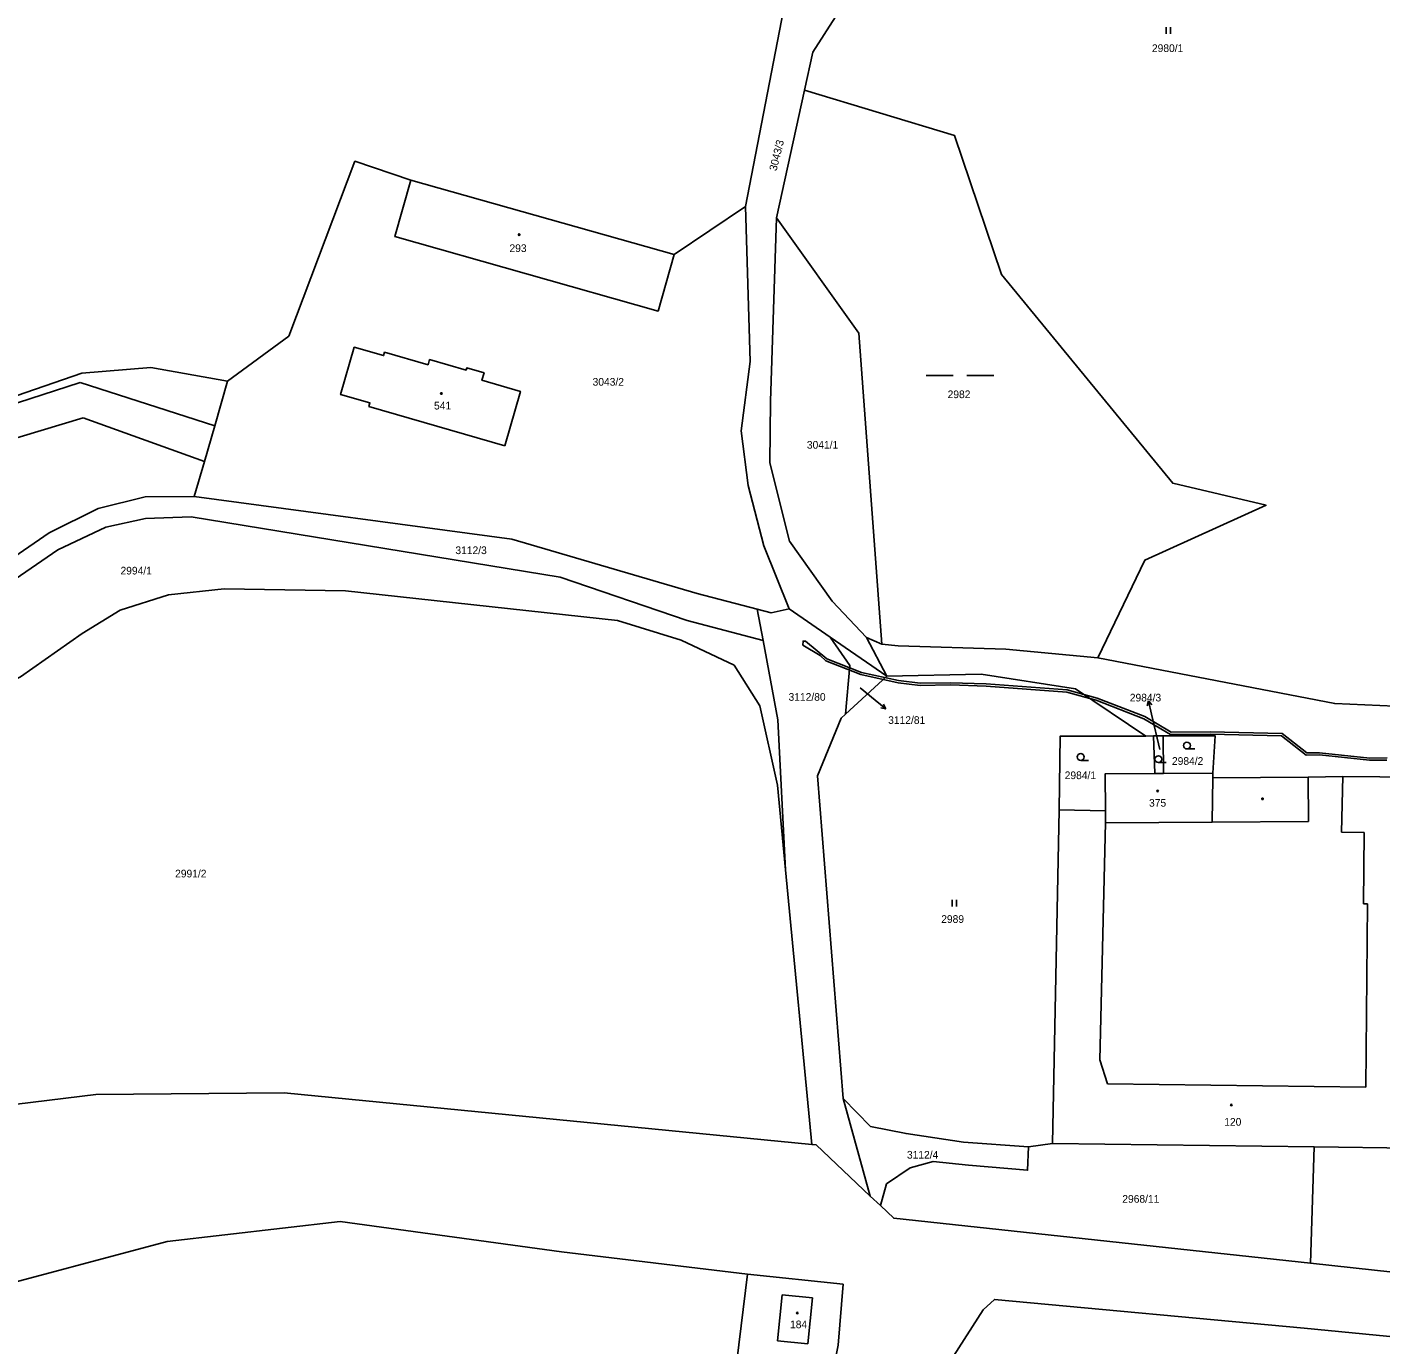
# Model space of a CAD drawing. Extents: x -776734 to -748832, y -1118122 to -976986.
# Drawn here: x -755036.1 to -754735.9, y -1113434.4 to -1113142 of the extents above; entities that cross this region are included whole.
import ezdxf

# ---------------------------------------------------------------- set-up
doc = ezdxf.new("R2010")
doc.units = 0
for name, color, linetype in [('KM_Hranice parcel', 7, 'Continuous'), ('KM_Parcelní čísla', 7, 'Continuous'), ('KM_Pop  PČ popisy', 7, 'Continuous'), ('KM_Vnitřní kresba', 7, 'Continuous'), ('KM_Věcná břemena k části', 7, 'Continuous'), ('KM_Značky budov', 7, 'Continuous'), ('KM_Značky kultur', 7, 'Continuous')]:
    doc.layers.add(name, color=color, linetype=linetype)

msp = doc.modelspace()

# ---------------------------------------------------------------- linework, layer by layer
at = {"layer": 'KM_Hranice parcel'}
for p, q in [((-754863.72, -1113156.03), (-754869.94, -1113184.37)), ((-754892.65, -1113192.47), (-754951.06, -1113175.96)), ((-754892.65, -1113192.47), (-754876.8, -1113181.8)), ((-755024.36, -1113220.91), (-754994.54, -1113230.49)), ((-754991.69, -1113220.6), (-754994.54, -1113230.49)), ((-754996.82, -1113238.38), (-755023.74, -1113228.7)), ((-754994.54, -1113230.49), (-754996.82, -1113238.38)), ((-754999.06, -1113246.17), (-754996.82, -1113238.38)), ((-754872.91, -1113278.1), (-754874.21, -1113271.18)), ((-754867.15, -1113271.08), (-754858.08, -1113277.36)), ((-754858.08, -1113277.36), (-754845.51, -1113286.05)), ((-754845.51, -1113286.05), (-754849.99, -1113277.44)), ((-754849.99, -1113277.44), (-754846.6, -1113278.91)), ((-754845.51, -1113286.05), (-754854.65, -1113294.42)), ((-754788.07, -1113299.3), (-754786.37, -1113299.29)), ((-754786.37, -1113299.29), (-754784.2, -1113299.29)), ((-754786.05, -1113307.61), (-754786.37, -1113299.29)), ((-754784.2, -1113299.29), (-754784.1, -1113307.6)), ((-754784.1, -1113307.6), (-754786.05, -1113307.61)), ((-754773.2, -1113307.52), (-754784.1, -1113307.6)), ((-754773.2, -1113308.57), (-754773.2, -1113307.52)), ((-754807.25, -1113315.67), (-754808.75, -1113389.67)), ((-754797.02, -1113315.93), (-754807.25, -1113315.67)), ((-754862.13, -1113389.91), (-754867.94, -1113328.97)), ((-754855.18, -1113379.69), (-754849.14, -1113401.34)), ((-754808.75, -1113389.67), (-754814.04, -1113390.4)), ((-754808.75, -1113389.67), (-754750.75, -1113390.44)), ((-754751.53, -1113416.27), (-754750.75, -1113390.44)), ((-754750.75, -1113390.44), (-754729.18, -1113390.74)), ((-754846.91, -1113403.45), (-754849.14, -1113401.34)), ((-754876.41, -1113418.71), (-754855.14, -1113420.87))]:
    msp.add_line(p, q, dxfattribs=at)
for points in [[(-754876.8, -1113181.8), (-754867.92, -1113135.91), (-754868.05, -1113104.5), (-754872.69, -1113085.2), (-754875.35, -1113079.52)], [(-754863.4, -1113082.6), (-754862.14, -1113085.88), (-754857.77, -1113108.41), (-754856.89, -1113139.77), (-754861.88, -1113147.63), (-754863.72, -1113156.03)], [(-755271.99, -1113090.82), (-755203.36, -1113173.85), (-755194.33, -1113180.41), (-755178.9, -1113182.49), (-755170.78, -1113184.63), (-755163.56, -1113188.38), (-755152.18, -1113198.82), (-755136.79, -1113213.94), (-755123.32, -1113222.34), (-755100.26, -1113228.77), (-755075.61, -1113229.77), (-755042.7, -1113225.27), (-755023.99, -1113218.77), (-755008.73, -1113217.54), (-754991.69, -1113220.6)], [(-754863.72, -1113156.03), (-754830.47, -1113166.06), (-754820.07, -1113196.9), (-754782.06, -1113243.24), (-754761.39, -1113248.09), (-754788.23, -1113260.27), (-754798.66, -1113281.97)], [(-754991.69, -1113220.6), (-754978.07, -1113210.56), (-754963.43, -1113171.79), (-754951.06, -1113175.96)], [(-754951.06, -1113175.96), (-754954.61, -1113188.52), (-754896.2, -1113205.03), (-754892.65, -1113192.47)], [(-754867.15, -1113271.08), (-754872.78, -1113257.09), (-754876.2, -1113243.72), (-754877.78, -1113231.6), (-754875.8, -1113216.25), (-754876.8, -1113181.8)], [(-754869.94, -1113184.37), (-754871.31, -1113225.02), (-754871.39, -1113238.69), (-754867.07, -1113256.05), (-754857.6, -1113269.39), (-754849.99, -1113277.44)], [(-754869.94, -1113184.37), (-754851.67, -1113209.94), (-754846.6, -1113278.91)], [(-754930.2, -1113234.9), (-754926.74, -1113222.86), (-754935.27, -1113220.39), (-754934.8, -1113218.76), (-754938.64, -1113217.65), (-754938.78, -1113218.13), (-754946.88, -1113215.78), (-754947.22, -1113216.93), (-754956.87, -1113214.15), (-754957.1, -1113214.92), (-754963.57, -1113213.05), (-754966.61, -1113223.54), (-754960.13, -1113225.41), (-754960.35, -1113226.17), (-754930.2, -1113234.9)], [(-755158.62, -1113218.61), (-755108.52, -1113234.11), (-755071.57, -1113236.21), (-755024.36, -1113220.91)], [(-755023.74, -1113228.7), (-755070.36, -1113242.74), (-755108.84, -1113241.5), (-755159.61, -1113226.16)], [(-755120.7, -1113319.55), (-755113.95, -1113312.75), (-755104.46, -1113304.58), (-755031.27, -1113254.22), (-755020.41, -1113248.82), (-755009.94, -1113246.24), (-754999.06, -1113246.17)], [(-754999.06, -1113246.17), (-754928.64, -1113255.61), (-754887.53, -1113267.69), (-754874.21, -1113271.18)], [(-754872.91, -1113278.1), (-754889.79, -1113273.69), (-754917.91, -1113264.06), (-754999.78, -1113250.7), (-755009.85, -1113251.04), (-755018.69, -1113252.95), (-755029.32, -1113258.02), (-755101.96, -1113307.9), (-755110.99, -1113316.94), (-755117.61, -1113328.97)], [(-754867.94, -1113328.97), (-754869.73, -1113310.2), (-754873.67, -1113292.58), (-754879.34, -1113283.56), (-754891.12, -1113278.02), (-754905.23, -1113273.67), (-754965.5, -1113267.11), (-754992.42, -1113266.68), (-755004.79, -1113267.98), (-755015.53, -1113271.37), (-755023.91, -1113276.56), (-755037.57, -1113286.2), (-755092.28, -1113314.49), (-755100.65, -1113318.43), (-755105.93, -1113322.81), (-755108.91, -1113328.1), (-755109.95, -1113335.16), (-755109.4, -1113341.3), (-755094.9, -1113384.72), (-755087.39, -1113386.98)], [(-754874.21, -1113271.18), (-754871.14, -1113271.98), (-754867.15, -1113271.08)], [(-754867.94, -1113328.97), (-754869.62, -1113295.67), (-754872.91, -1113278.1)], [(-754854.65, -1113294.42), (-754853.7, -1113283.67), (-754858.08, -1113277.36)], [(-754846.6, -1113278.91), (-754842.97, -1113279.27), (-754819.11, -1113280.03), (-754798.66, -1113281.97)], [(-754798.66, -1113281.97), (-754746.14, -1113292.12), (-754732.8, -1113292.68)], [(-754788.07, -1113299.3), (-754803.63, -1113288.86), (-754824.53, -1113285.55), (-754845.51, -1113286.05)], [(-754854.65, -1113294.42), (-754855.62, -1113295.31), (-754860.85, -1113308.15), (-754855.18, -1113379.69)], [(-754807.25, -1113315.67), (-754807.05, -1113299.34), (-754788.07, -1113299.3)], [(-754784.2, -1113299.29), (-754772.65, -1113299.26), (-754773.2, -1113307.52)], [(-754786.05, -1113307.61), (-754797.07, -1113307.69), (-754797.02, -1113315.93)], [(-754773.2, -1113308.57), (-754773.33, -1113318.39), (-754797, -1113318.56), (-754797.02, -1113315.93)], [(-754773.2, -1113308.57), (-754752.04, -1113308.41), (-754744.33, -1113308.31), (-754727.93, -1113308.42)], [(-754862.13, -1113389.91), (-754979.13, -1113378.43), (-755020.88, -1113378.84), (-755087.39, -1113386.98)], [(-754855.18, -1113379.69), (-754849.09, -1113385.91), (-754841.21, -1113387.49), (-754828.5, -1113389.4), (-754814.04, -1113390.4)], [(-754849.14, -1113401.34), (-754861.13, -1113390.01), (-754862.13, -1113389.91)], [(-754814.04, -1113390.4), (-754814.27, -1113395.63), (-754827.37, -1113394.5), (-754835.2, -1113393.68), (-754840.28, -1113395.09), (-754845.54, -1113398.67), (-754846.91, -1113403.45)], [(-754751.53, -1113416.27), (-754843.93, -1113406.26), (-754846.91, -1113403.45)], [(-754876.41, -1113418.71), (-754917.66, -1113413.7), (-754966.68, -1113407.01), (-755005.06, -1113411.4), (-755047.8, -1113422.83)], [(-754751.53, -1113416.27), (-754677.81, -1113424.26), (-754654.29, -1113427.93), (-754581.73, -1113435.77), (-754565.85, -1113437.51), (-754555.87, -1113438.3), (-754517.87, -1113439.7), (-754508.05, -1113440.3)], [(-754876.41, -1113418.71), (-754878.78, -1113437.98), (-754857.28, -1113439.65)], [(-754855.14, -1113420.87), (-754856.3, -1113434.4), (-754857.28, -1113439.65)], [(-754618.09, -1113442.69), (-754679.15, -1113437.81), (-754752.93, -1113430.66), (-754821.61, -1113424.27), (-754824.15, -1113426.56), (-754841.49, -1113453.72)]]:
    msp.add_lwpolyline(points, dxfattribs=at)
at = {"layer": 'KM_Pop  PČ popisy'}
for p, q in [((-754851.41, -1113288.63), (-754848.07, -1113291.38)), ((-754848.07, -1113291.38), (-754845.738, -1113293.269)), ((-754787.455, -1113291.506), (-754787.718, -1113292.594)), ((-754786.78, -1113294.43), (-754787.455, -1113291.506)), ((-754787.455, -1113291.506), (-754786.742, -1113292.369)), ((-754845.738, -1113293.269), (-754846.831, -1113293.027)), ((-754845.738, -1113293.269), (-754846.201, -1113292.249)), ((-754784.92, -1113302.26), (-754786.78, -1113294.43))]:
    msp.add_line(p, q, dxfattribs=at)
at = {"layer": 'KM_Vnitřní kresba'}
for p, q in [((-754751.95, -1113318.23), (-754752.04, -1113308.41)), ((-754744.33, -1113308.31), (-754744.63, -1113320.66)), ((-754798.21, -1113371.14), (-754797, -1113318.56)), ((-754773.33, -1113318.39), (-754751.95, -1113318.23)), ((-754744.63, -1113320.66), (-754739.63, -1113320.71)), ((-754739.63, -1113320.71), (-754739.74, -1113336.49)), ((-754739.74, -1113336.49), (-754738.92, -1113336.5)), ((-754738.92, -1113336.5), (-754739.22, -1113377.2)), ((-754796.53, -1113376.42), (-754798.21, -1113371.14)), ((-754739.22, -1113377.2), (-754796.53, -1113376.42)), ((-754868.71, -1113423.29), (-754869.74, -1113433.45)), ((-754861.98, -1113423.95), (-754868.71, -1113423.29)), ((-754863.02, -1113434.1), (-754861.98, -1113423.95)), ((-754869.74, -1113433.45), (-754863.02, -1113434.1))]:
    msp.add_line(p, q, dxfattribs=at)
at = {"layer": 'KM_Věcná břemena k části'}
msp.add_lwpolyline([(-754805.47, -1113289.07), (-754823.43, -1113287.71), (-754831.38, -1113287.47), (-754838.08, -1113287.56), (-754842.87, -1113286.99), (-754851.11, -1113285.2), (-754858.77, -1113282.19), (-754863.55, -1113278.26), (-754864.05, -1113278.22), (-754864.11, -1113279.12), (-754860.23, -1113281.42), (-754859.01, -1113282.63), (-754851.25, -1113285.68), (-754842.95, -1113287.49), (-754838.1, -1113288.06), (-754831.38, -1113287.97), (-754823.45, -1113288.21), (-754805.55, -1113289.57), (-754800.49, -1113290.97), (-754801.81, -1113290.08)], close=True, dxfattribs=at)
msp.add_lwpolyline([(-754734.55, -1113304.13), (-754738.39, -1113304.18), (-754749.51, -1113303), (-754752.32, -1113303.01), (-754757.81, -1113298.76), (-754773.77, -1113298.36), (-754782.41, -1113298.47), (-754788.3, -1113295), (-754798.87, -1113290.89), (-754801.81, -1113290.08), (-754800.49, -1113290.97), (-754799.03, -1113291.37), (-754788.52, -1113295.46), (-754782.55, -1113298.97), (-754773.77, -1113298.86), (-754757.99, -1113299.26), (-754752.5, -1113303.51), (-754749.53, -1113303.5), (-754738.41, -1113304.68), (-754734.57, -1113304.63)], dxfattribs=at)
at = {"layer": 'KM_Značky budov'}
for centre in [(-754927.0068, -1113188.0692), (-754944.2568, -1113223.3092), (-754785.4368, -1113311.4992), (-754762.1668, -1113313.2392), (-754769.0668, -1113381.1492), (-754865.3468, -1113427.2792)]:
    msp.add_circle(centre, 0.175, dxfattribs=at)
at = {"layer": 'KM_Značky kultur'}
for p, q in [((-754783.571, -1113143.55), (-754783.571, -1113142.05)), ((-754782.57, -1113143.55), (-754782.57, -1113142.05)), ((-754836.759, -1113219.31), (-754830.759, -1113219.31)), ((-754827.759, -1113219.31), (-754821.759, -1113219.31)), ((-754778.923, -1113302.17), (-754777.173, -1113302.17)), ((-754802.493, -1113304.7), (-754800.743, -1113304.7)), ((-754785.263, -1113305.18), (-754783.513, -1113305.18)), ((-754831.011, -1113337.15), (-754831.011, -1113335.65)), ((-754830.01, -1113337.15), (-754830.01, -1113335.65))]:
    msp.add_line(p, q, dxfattribs=at)
for centre in [(-754778.9229, -1113301.4198), (-754802.4929, -1113303.9498), (-754785.2629, -1113304.4298)]:
    msp.add_circle(centre, 0.75, dxfattribs=at)

# ---------------------------------------------------------------- texts
at = {"layer": 'KM_Parcelní čísla'}
for s, p in [('2980/1', (-754786.69, -1113147.56)), ('293', (-754929.16, -1113191.93)), ('3043/2', (-754910.73, -1113221.58)), ('2982', (-754832, -1113224.34)), ('541', (-754945.9, -1113226.86)), ('3041/1', (-754863.21, -1113235.55)), ('3112/3', (-754941.15, -1113258.94)), ('2994/1', (-755015.42, -1113263.46)), ('3112/80', (-754867.276, -1113291.48)), ('2984/3', (-754791.597, -1113291.63)), ('3112/81', (-754845.18, -1113296.608)), ('2984/2', (-754782.247, -1113305.69)), ('2984/1', (-754806.037, -1113308.86)), ('375', (-754787.33, -1113314.97)), ('2991/2', (-755003.31, -1113330.66)), ('2989', (-754833.42, -1113340.75)), ('120', (-754770.65, -1113385.74)), ('3112/4', (-754841.02, -1113393.04)), ('2968/11', (-754793.26, -1113402.83)), ('184', (-754866.95, -1113430.67))]:
    msp.add_text(s, height=1.7, dxfattribs=at).set_placement(p)
msp.add_text('3043/3', height=1.7, rotation=76, dxfattribs=at).set_placement((-754869.945, -1113174.045))

doc.saveas('drawing.dxf')
